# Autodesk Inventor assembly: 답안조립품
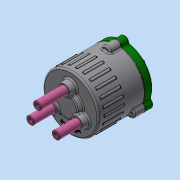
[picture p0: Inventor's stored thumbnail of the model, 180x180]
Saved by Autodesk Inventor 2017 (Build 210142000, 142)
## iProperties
Part Number: 답안조립품
Material: 일반
Document SubType Name: Assembly
Designer: MRC
Mass: 2354.47 g
Surface Area: 1884.92 cm^2
Volume: 517.816 cm^3
Density: 4.54692 g/cm^3
Author: MRC
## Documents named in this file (15)
- C:\Users\MRC\Desktop\620811V1009\답안조립품.iam
- C:\Users\MRC\Desktop\620811V1009\본체.ipt
- C:\Users\MRC\Desktop\620811V1009\개스킷.ipt
- C:\Users\MRC\Desktop\620811V1009\커버.ipt
- C:\Users\MRC\Desktop\620811V1009\베어링 NA 4900.ipt
- C:\Users\MRC\Desktop\620811V1009\오일 실.ipt
- C:\Users\MRC\Desktop\620811V1009\메인 축.ipt
- C:\Users\MRC\Desktop\620811V1009\멈춤링 22x1.2.ipt
- C:\Users\MRC\Desktop\620811V1009\판캠.ipt
- C:\Users\MRC\Desktop\620811V1009\멈춤링 10x1.ipt
- C:\Users\MRC\Desktop\620811V1009\볼트 M5.ipt
- C:\Users\MRC\Desktop\620811V1009\슬라이드 축.ipt
- C:\Users\MRC\Desktop\620811V1009\가변스프링1.ipt
- C:\Users\MRC\Desktop\620811V1009\가변스프링2.ipt
- C:\Users\MRC\Desktop\620811V1009\가변스프링3.ipt
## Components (4 placed, 4 different names)
1. 개스킷:1
2. 가변스프링1:1
3. 가변스프링2:1
4. 가변스프링3:1
